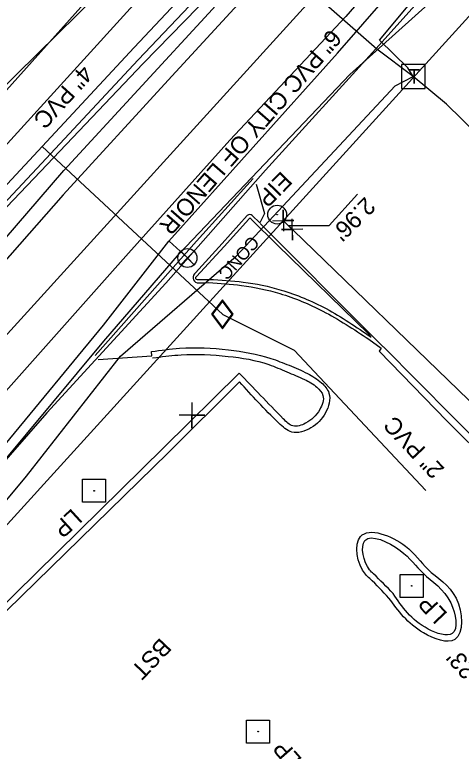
# Model space of a CAD drawing. Extents: x 1263837 to 1268319, y 770628 to 773628.
# Drawn here: x 1266959.5 to 1267064.1, y 772261.5 to 772434.2 of the extents above; entities that cross this region are included whole.
import ezdxf

# ---------------------------------------------------------------- set-up
doc = ezdxf.new("R2010")
doc.units = 0
for name, color, linetype in [('Default', 7, 'Continuous'), ('Exist DTM Spot Elevation CELL', 7, 'Continuous'), ('Exist Property Iron Pin Text', 7, 'Continuous'), ('Exist Roads EOP Other', 7, 'Continuous'), ('Exist Roads EOP Other Text', 7, 'Continuous'), ('Exist Roads EOT Text', 7, 'Continuous'), ('Exist Structure Minor Catch Basin Top Elevation', 7, 'Continuous'), ('Exist Utilities Gas UG Line SUE LOS B', 7, 'Continuous'), ('Exist Utilities Gas UG Line SUE LOS B Text', 7, 'Continuous'), ('Exist Utilities Gas Valve CELL', 7, 'Continuous'), ('Exist Utilities Other Pole With Base CELL', 7, 'Continuous'), ('Exist Utilities Other Pole With Base Text', 7, 'Continuous'), ('Exist Utilities Telephone Pedestal CELL', 7, 'Continuous'), ('Exist Utilities Telephone UG Cable SUE LOS B', 7, 'Continuous'), ('Exist Utilities Telephone UG FO SUE LOS B', 7, 'Continuous'), ('Exist Utilities Water UG Line SUE LOS B', 7, 'Continuous'), ('Exist Utilities Water UG Line SUE LOS B Text', 7, 'Continuous'), ('Exist Utilities Water Valve CELL', 7, 'Continuous'), ('Prop Conc 4in Sidewalk', 7, 'Continuous'), ('Prop Drainage Structure Pipe RCP 18in Contractor Design Label', 7, 'Continuous'), ('Prop Drainage Structure Pipe RCP 60in Class III', 7, 'Continuous'), ('Prop Drainage Structure Pipe Side Drain 15in', 7, 'Continuous'), ('Prop Guardrail', 7, 'Continuous'), ('Prop Horizontal Alignment', 7, 'Continuous'), ('Prop SS Fill Line', 7, 'Continuous'), ('Prop SS Fill Text', 7, 'Continuous'), ('Prop SS Transition Line', 7, 'Continuous'), ('Scratch_Level_2', 7, 'Continuous')]:
    doc.layers.add(name, color=color, linetype=linetype)

# ---------------------------------------------------------------- blocks, each defined once
blk = doc.blocks.new('EXIST PROPERTY IRON PIN')
at = {"layer": 'Prop Conc 4in Sidewalk'}
for radius in [0.0441, 0.00141]:
    blk.add_circle((0, 0), radius, dxfattribs=at)
blk = doc.blocks.new('EXIST UTILITIES OTHER POLE WITH BASE')
at = {"layer": 'Exist Utilities Other Pole With Base CELL'}
blk.add_line((0, 0), (0, 0), dxfattribs=at)
blk.add_lwpolyline([(-0.0545, 0.054), (0.0535, 0.054), (0.0535, -0.054), (-0.0545, -0.054), (-0.0545, 0.054)], dxfattribs=at)
blk.add_circle((0, 0), 0.00141, dxfattribs=at)
blk = doc.blocks.new('EXIST DTM SPOT ELEVATION')
at = {"layer": 'Exist DTM Spot Elevation CELL'}
blk.add_lwpolyline([(0, 0.06), (0, -0.06), (0, 0), (0.06, 0), (-0.06, 0)], dxfattribs=at)
blk = doc.blocks.new('EXIST UTILITIES TELEPHONE PEDESTAL')
at = {"layer": 'Exist Utilities Telephone Pedestal CELL'}
blk.add_line((0, 0), (0, 0), dxfattribs=at)
blk.add_lwpolyline([(-0.0545, -0.0565), (0.0574, -0.0565), (0.0574, 0.0554), (-0.0545, 0.0554), (-0.0545, -0.0565)], dxfattribs=at)
blk.add_text('T', height=0.0684, dxfattribs=at).set_placement((-0.0226, -0.0343))
blk = doc.blocks.new('EXIST UTILITIES WATER VALVE')
at = {"layer": 'Exist Utilities Water Valve CELL'}
blk.add_lwpolyline([(0.0315, 0.0315), (-0.0315, -0.0315), (0, 0), (0.0315, -0.0315), (-0.0315, 0.0315)], dxfattribs=at)
blk.add_circle((0, 0), 0.0445, dxfattribs=at)
blk = doc.blocks.new('EXIST UTILITIES GAS VALVE')
at = {"layer": 'Exist Utilities Gas Valve CELL'}
blk.add_line((0, 0), (0, 0), dxfattribs=at)
blk.add_lwpolyline([(0, 0.0683), (-0.0508, 0), (0, -0.0683), (0.0508, 0), (0, 0.0683)], dxfattribs=at)
blk.add_lwpolyline([(0.0458, 0), (0, 0.0615), (-0.0458, 0), (0, -0.0615)], close=True, dxfattribs=at)

msp = doc.modelspace()

# ---------------------------------------------------------------- linework, layer by layer
at = {"layer": 'Default'}
msp.add_line((1266965.89, 772403.36), (1267008.27, 772363.93), dxfattribs=at)
at = {"layer": 'Exist Roads EOP Other'}
msp.add_lwpolyline([(1267017, 772385.32), (1267043.35, 772358.88), (1267045.8, 772356.4)], dxfattribs=at)
at = {"layer": 'Exist Utilities Gas UG Line SUE LOS B'}
msp.add_line((1266965.89, 772403.36), (1267008.27, 772363.93), dxfattribs=at)
for points in [[(1266826.01, 772260.15), (1266857.65, 772289.14), (1266895.03, 772326.45), (1266944.34, 772380.2), (1266987.5, 772426.58), (1267020.79, 772462.03)], [(1267008.27, 772363.93), (1267024.96, 772355.55), (1267055.84, 772322.67)]]:
    msp.add_lwpolyline(points, dxfattribs=at)
at = {"layer": 'Exist Utilities Telephone UG Cable SUE LOS B'}
for points in [[(1267052.83, 772419.78), (1267044.36, 772426.17), (1267016.25, 772450.85), (1266994.43, 772469.13), (1266973.54, 772492.2), (1266959.83, 772514.6)], [(1266894.85, 772231.77), (1266893.08, 772233.4), (1266890.92, 772236.91), (1266894.43, 772241.95), (1266895.81, 772246.91), (1266901.85, 772256.59), (1266913.6, 772269.64), (1266885.36, 772298.67), (1266907.53, 772324.36), (1266940.1, 772361.84), (1266971, 772397.71), (1267005.88, 772435.55), (1267039.51, 772473.7), (1267071.13, 772508.4)], [(1266894.82, 772231.62), (1266882.54, 772238.29), (1266881.5, 772240.54), (1266906.85, 772271.5), (1266931.58, 772297.61), (1266956.08, 772328.45), (1266980.39, 772357.69), (1266998.14, 772378.22), (1267038.01, 772420.21), (1267067.86, 772447.15), (1267100, 772481.26)], [(1266895.06, 772232.03), (1266893.39, 772235.54), (1266896.93, 772242.02), (1266900.69, 772251.07), (1266914.56, 772265.21), (1266919.81, 772277.36), (1266935.14, 772293.55), (1266962.27, 772326.03), (1266984.26, 772354.2), (1267011.39, 772377.61), (1267048.61, 772417.53), (1267052.83, 772419.78)], [(1267101.36, 772372.94), (1267092.86, 772381.75), (1267060.66, 772413.3), (1267052.83, 772419.78)]]:
    msp.add_lwpolyline(points, dxfattribs=at)
at = {"layer": 'Exist Utilities Telephone UG FO SUE LOS B'}
for points in [[(1266814.85, 772276.3), (1266828.4, 772281.15), (1266850.03, 772305.04), (1266875.42, 772334.02), (1266901.87, 772361.16), (1266928.35, 772388.2), (1266955.12, 772415.65), (1266978.94, 772439.07), (1267008.37, 772468.81), (1267035.48, 772497.08), (1267058.14, 772518.7), (1267085.04, 772546.33), (1267108.31, 772568.88), (1267130.45, 772592.84), (1267151.19, 772617.71), (1267175.93, 772646.52), (1267201.12, 772673.74)], [(1267052.83, 772419.78), (1267051.59, 772421.75), (1267044.97, 772428.27), (1267062.65, 772449.51), (1267094.39, 772485.05)]]:
    msp.add_lwpolyline(points, dxfattribs=at)
at = {"layer": 'Exist Utilities Water UG Line SUE LOS B'}
for p, q in [((1266955.45, 772414.3), (1267015.09, 772480.76)), ((1266995.66, 772381.18), (1266999.96, 772377.2))]:
    msp.add_line(p, q, dxfattribs=at)
msp.add_lwpolyline([(1266929.23, 772298.39), (1266957.23, 772333.47), (1266980.31, 772361.45), (1266995.62, 772381.13), (1267035.16, 772425.19), (1267052.38, 772445.1), (1267064.16, 772457.86), (1267094.36, 772490.84)], dxfattribs=at)
at = {"layer": 'Prop Drainage Structure Pipe RCP 60in Class III'}
for p, q in [((1267022.43, 772385.97), (1267022.43, 772385.97)), ((1267024.55, 772383.91), (1267024.55, 772383.91))]:
    msp.add_line(p, q, dxfattribs=at)
for points in [[(1267019.93, 772385.93), (1267024.93, 772386.01), (1267022.43, 772385.97), (1267022.39, 772388.47), (1267022.47, 772383.47)], [(1267027.05, 772383.95), (1267022.05, 772383.87), (1267024.55, 772383.91), (1267024.59, 772381.41), (1267024.51, 772386.41)]]:
    msp.add_lwpolyline(points, dxfattribs=at)
at = {"layer": 'Prop Drainage Structure Pipe Side Drain 15in'}
msp.add_lwpolyline([(1267023.67, 772384.78), (1267033.17, 772384.81), (1267039.81, 772392.13)], dxfattribs=at)
at = {"layer": 'Prop Guardrail'}
for p in [(1267173.2, 772239.88), (1267024.55, 772383.91)]:
    msp.add_line(p, (1267022.43, 772385.97), dxfattribs=at)
at = {"layer": 'Prop Horizontal Alignment'}
for p, q in [((1267380.31, 772869.08), (1266850.44, 772285.9)), ((1267424.71, 772828.73), (1266891.83, 772242.23))]:
    msp.add_line(p, q, dxfattribs=at)
at = {"layer": 'Prop SS Fill Line'}
for p, q in [((1267020.98, 772380.32), (1267014.93, 772386.3)), ((1266991.82, 772353.77), (1266992.73, 772353.88))]:
    msp.add_line(p, q, dxfattribs=at)
for points in [[(1267014.32, 772386.29), (1267008.6, 772379.9), (1267002.06, 772372.84)], [(1267043, 772358.66), (1267042.48, 772359.3), (1267020.98, 772380.32)], [(1267002.28, 772372.19), (1267004.07, 772372.18), (1267005.1, 772372.19)], [(1267045.91, 772356.33), (1267061.99, 772340.1), (1267082.07, 772320.07)], [(1267012.1, 772350.21), (1266994.35, 772332.71), (1266949.59, 772288.68), (1266927.9, 772267.59)]]:
    msp.add_lwpolyline(points, dxfattribs=at)
for centre, major_axis, ratio, start_param, end_param in [((1267014.63, 772386.15), (0.12, 0.318), 0.99486, 5.527212, 7.807503), ((1267002.19, 772372.52), (-0.339, 0.068), 0.991403, 5.315353, 8.302567)]:
    msp.add_ellipse(centre, major_axis=major_axis, ratio=ratio, start_param=start_param, end_param=end_param, dxfattribs=at)
for points in [[(1267005.1, 772372.19), (1267013.05, 772371.56), (1267021.91, 772369.68), (1267032.46, 772365.33), (1267043, 772358.66)], [(1266992.73, 772353.88), (1266998.46, 772354.5), (1267009.48, 772354.13), (1267019.04, 772352.22), (1267023.25, 772350.51), (1267027.38, 772348.72), (1267030.33, 772346.89), (1267031.73, 772344.97), (1267030.97, 772341.65), (1267027.64, 772338.45), (1267024.69, 772337.82), (1267022.43, 772339.48), (1267012.1, 772350.21)], [(1267048.2, 772298.51), (1267056.39, 772290.19), (1267062.03, 772289.15), (1267061.67, 772296.31), (1267055.2, 772303.28), (1267049.8, 772308.62), (1267041.57, 772310.94), (1267042.66, 772304.06), (1267043.58, 772303.12), (1267048.2, 772298.51)]]:
    msp.add_spline(points, degree=3, dxfattribs=at)
at = {"layer": 'Prop SS Fill Text'}
for p, q in [((1267013.96, 772387.18), (1267008.07, 772380.59)), ((1267008.07, 772380.59), (1267001.87, 772373.7)), ((1267002.23, 772371.36), (1267003.89, 772371.4)), ((1267003.89, 772371.4), (1267004.99, 772371.43))]:
    msp.add_line(p, q, dxfattribs=at)
for points in [[(1267204.74, 772651.92), (1267177.02, 772621.14), (1267149.1, 772590.18), (1267145.46, 772586.44), (1267139.98, 772584.67), (1267116.53, 772558.83), (1267115.92, 772554.65), (1267085.25, 772524.39), (1267078.79, 772520.73), (1267070.08, 772511.46), (1267043.47, 772484.13), (1267032.44, 772472.27), (1267031.66, 772469.68), (1267016.92, 772453.79), (1266988.45, 772423.67), (1266964.67, 772398.15), (1266936.57, 772368.17), (1266907.1, 772336.97), (1266877.6, 772304.96), (1266855.4, 772281.41), (1266833.42, 772261.44)], [(1267200.2, 772600.69), (1267172.19, 772569.47), (1267160.06, 772555.77), (1267156.65, 772548.15), (1267144.98, 772534.79), (1267113.45, 772499.8), (1267104.44, 772488.92), (1267097.3, 772485.11), (1267071.59, 772456.86), (1267044.09, 772426.25), (1267018.23, 772397.83), (1266994.88, 772371.31), (1266966.99, 772340.9), (1266937.4, 772307.04), (1266908.92, 772274.6), (1266890.12, 772250.31)], [(1267016.07, 772394.49), (1267018.04, 772387.6), (1267016.9, 772385.42), (1267015.15, 772387.16)], [(1267042.48, 772358.15), (1267045.36, 772356.07), (1267044.91, 772355.35), (1267060.79, 772339.05), (1267081.02, 772318.95)], [(1266979.01, 772353.39), (1266991.61, 772354.26), (1266991.57, 772355.27)], [(1267012.14, 772348.16), (1266995.49, 772331.55), (1266950.69, 772287.82), (1266929.93, 772267.49)]]:
    msp.add_lwpolyline(points, dxfattribs=at)
for centre, major_axis, ratio, start_param, end_param in [((1267014.54, 772386.52), (0.815, 0.345), 0.996702, 0.404573, 1.885962), ((1267002.58, 772372.61), (-1.08, -0.74), 0.994431, 4.686878, 6.988889)]:
    msp.add_ellipse(centre, major_axis=major_axis, ratio=ratio, start_param=start_param, end_param=end_param, dxfattribs=at)
for points in [[(1267004.99, 772371.43), (1267012.64, 772370.76), (1267021.63, 772368.85), (1267031.68, 772364.74), (1267042.48, 772358.15)], [(1266991.57, 772355.27), (1266998.14, 772356.02), (1267009.57, 772355.67), (1267019.5, 772353.66), (1267023.79, 772352.03), (1267028.1, 772350.11), (1267031.39, 772347.93), (1267033.12, 772345.52), (1267032.31, 772340.88), (1267028.91, 772337.35), (1267024.43, 772336.39), (1267021.37, 772338.5), (1267012.14, 772348.16)], [(1267047.2, 772297.44), (1267055.29, 772289.29), (1267062.62, 772287.74), (1267062.92, 772297.42), (1267056.28, 772304.25), (1267051.06, 772309.65), (1267040.55, 772311.92), (1267041.66, 772303.05), (1267042.7, 772302.02), (1267047.2, 772297.44)]]:
    msp.add_spline(points, degree=3, dxfattribs=at)
at = {"layer": 'Prop SS Transition Line'}
for points in [[(1267395.07, 772827.56), (1267364.93, 772795.4), (1267333.45, 772761.5), (1267304.93, 772730.59), (1267278.73, 772701.98), (1267250.02, 772670.21), (1267221.06, 772638.24), (1267193.05, 772607.16), (1267162.88, 772573.94), (1267133.95, 772541.76), (1267103.89, 772508.37), (1267089.63, 772492.49), (1267063.41, 772464.33), (1267037.06, 772433.84), (1267009.94, 772404.86), (1266986.14, 772378.32), (1266959.27, 772348.06), (1266929.7, 772314.83), (1266900.08, 772282.12), (1266879.74, 772258.85), (1266856.83, 772233.08), (1266828.41, 772200.91)], [(1267146.37, 772585.85), (1267115.99, 772554.09), (1267086.36, 772523.32), (1267072.65, 772509.07), (1267045.87, 772481.1), (1267018.57, 772452.6), (1266989.57, 772422.83), (1266965.51, 772397.48), (1266937.05, 772367.65)], [(1267131.64, 772569.99), (1267100.94, 772535.83), (1267088.17, 772521.91), (1267074.85, 772507.02), (1267048.82, 772478.13), (1267022.71, 772448.59), (1266995.43, 772418.92), (1266970.81, 772392.01), (1266944.06, 772361.6), (1266914.36, 772330.24), (1266883.54, 772297.08), (1266863.59, 772273.71), (1266851.71, 772262.11), (1266827.22, 772236.18), (1266811.72, 772219.25)], [(1266978.38, 772354.32), (1267002.11, 772381.13), (1267015.38, 772395.81)]]:
    msp.add_lwpolyline(points, dxfattribs=at)
at = {"layer": 'Scratch_Level_2'}
msp.add_line((1267402.51, 772848.9), (1266783.44, 772167.55), dxfattribs=at)
msp.add_arc((1275094.23, 780056.99), 11459.16, 216.983333, 225.433333, dxfattribs=at)

# ---------------------------------------------------------------- block references
at = {"layer": 'Exist DTM Spot Elevation CELL', "xscale": 50, "yscale": 50}
msp.add_blockref('EXIST DTM SPOT ELEVATION', (1267001.02, 772340.32), dxfattribs=at)
at = {"layer": 'Exist Utilities Gas Valve CELL', "xscale": 50, "yscale": 50}
msp.add_blockref('EXIST UTILITIES GAS VALVE', (1267008.16, 772364), dxfattribs=at)
at = {"layer": 'Exist Utilities Other Pole With Base CELL', "xscale": 50, "yscale": 50}
for p in [(1266978.12, 772322.61), (1267052.53, 772300.32), (1267016.54, 772266.14)]:
    msp.add_blockref('EXIST UTILITIES OTHER POLE WITH BASE', p, dxfattribs=at)
at = {"layer": 'Exist Utilities Telephone Pedestal CELL', "xscale": 50, "yscale": 50}
msp.add_blockref('EXIST UTILITIES TELEPHONE PEDESTAL', (1267052.83, 772419.78), dxfattribs=at)
at = {"layer": 'Exist Utilities Water Valve CELL', "xscale": 50, "yscale": 50}
msp.add_blockref('EXIST UTILITIES WATER VALVE', (1266999.96, 772377.2), dxfattribs=at)
at = {"layer": 'Prop Conc 4in Sidewalk', "xscale": 50, "yscale": 50}
msp.add_blockref('EXIST PROPERTY IRON PIN', (1267020.99, 772387.36), dxfattribs=at)

# ---------------------------------------------------------------- texts
at = {"layer": 'Exist Property Iron Pin Text'}
msp.add_text('EIP', height=4, rotation=225.5929, dxfattribs=at).set_placement((1267021.99, 772397.76))
at = {"layer": 'Exist Roads EOP Other Text'}
msp.add_text('CONC', height=3, rotation=228.3212, dxfattribs=at).set_placement((1267014.85, 772382.63))
at = {"layer": 'Exist Roads EOT Text'}
msp.add_text('BST', height=4, rotation=226.3771, dxfattribs=at).set_placement((1266993.64, 772288.35))
at = {"layer": 'Exist Structure Minor Catch Basin Top Elevation'}
msp.add_text("TOP=1180.23'", height=4, rotation=131.3556, dxfattribs=at).set_placement((1267086.14, 772259.99))
at = {"layer": 'Exist Utilities Gas UG Line SUE LOS B Text'}
for s, rotation, p in [('4" PVC', 227.9782, (1266975.22, 772422.73)), ('2" PVC', 133.2059, (1267060.4, 772327.8))]:
    msp.add_text(s, height=4, rotation=rotation, dxfattribs=at).set_placement(p)
at = {"layer": 'Exist Utilities Other Pole With Base Text'}
for rotation, p in [(222.3821, (1266972.94, 772318.65)), (133.2503, (1267061.11, 772293.79)), (131.3556, (1267027.01, 772259.66))]:
    msp.add_text('LP', height=4, rotation=rotation, dxfattribs=at).set_placement(p)
at = {"layer": 'Exist Utilities Water UG Line SUE LOS B Text'}
msp.add_text('6" PVC CITY OF LENOIR', height=4, rotation=228.9178, dxfattribs=at).set_placement((1267033.43, 772431.11))
at = {"layer": 'Prop Drainage Structure Pipe RCP 18in Contractor Design Label'}
msp.add_text("2.96'", height=4, rotation=224.9951, dxfattribs=at).set_placement((1267041.6, 772391.75))

doc.saveas('drawing.dxf')
